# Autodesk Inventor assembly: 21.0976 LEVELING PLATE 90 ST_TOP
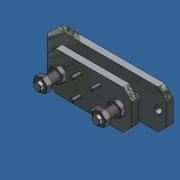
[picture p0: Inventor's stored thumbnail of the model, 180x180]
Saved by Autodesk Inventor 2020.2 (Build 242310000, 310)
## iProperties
Created: 2020-07
Part Number: 21.0976 LEVELING PLATE 90 ST_TOP
Document SubType Name: Assembly
Designer: amoles
Author: amoles
Sending System: MiniTec Maschinenbau GmbH & Co.KG
Major Version: 4.0
Minor Version: 0.0
Format Version: 0.0
Product Id: MiniTec Maschinenbau GmbH & Co.KG
Art.-Nr.: 21.0976/0
L: -
Stück: 1
5: Nivellierplatte 90 ST
7: 21.0976/0
8: MiniTec Maschinenbau GmbH & Co KG
Bestellnummer: 21.0976/0
Beschreibung: Nivellierplatte 90 ST
Länge: -
designation: hexagon screw
size: 0 x 75
standard: DIN 931
Description: hexagon screw
Artikelnr: 21.0976/0
Lieferant: MiniTec Maschinenbau GmbH & Co KG
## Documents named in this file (12)
- Y:\INVENTOR LIBRARIES\PARTS LIBRARY\FEET WHEELS FLOOR FASTENING SUPPORTS\21.0976 LEVELING PLATE 90 ST_TOP.iam
- Y:\INVENTOR LIBRARIES\PARTS LIBRARY\FEET WHEELS FLOOR FASTENING SUPPORTS\SUBCOMPONENTS\21.0976 SUBCOMPONENTS\21.0976 LEVELING PLATE 90 ST_TOP-21.ipt
- Y:\INVENTOR LIBRARIES\PARTS LIBRARY\FEET WHEELS FLOOR FASTENING SUPPORTS\SUBCOMPONENTS\21.0976 SUBCOMPONENTS\21.0976 LEVELING PLATE 90 ST_TOP 21_1.ipt
- Y:\INVENTOR LIBRARIES\PARTS LIBRARY\FEET WHEELS FLOOR FASTENING SUPPORTS\SUBCOMPONENTS\21.0976 SUBCOMPONENTS\21.0976 LEVELING PLATE 90 ST_TOP 21_2.ipt
- Y:\INVENTOR LIBRARIES\PARTS LIBRARY\FEET WHEELS FLOOR FASTENING SUPPORTS\SUBCOMPONENTS\21.0976 SUBCOMPONENTS\21.0976 LEVELING PLATE 90 ST_TOP 21_3.ipt
- Y:\INVENTOR LIBRARIES\PARTS LIBRARY\FEET WHEELS FLOOR FASTENING SUPPORTS\SUBCOMPONENTS\21.0976 SUBCOMPONENTS\21.0976 LEVELING PLATE 90 ST_TOP 21_4.ipt
- Y:\INVENTOR LIBRARIES\PARTS LIBRARY\FEET WHEELS FLOOR FASTENING SUPPORTS\SUBCOMPONENTS\21.0976 SUBCOMPONENTS\21.0976 LEVELING PLATE 90 ST_TOP 21_9.ipt
- Y:\INVENTOR LIBRARIES\PARTS LIBRARY\FEET WHEELS FLOOR FASTENING SUPPORTS\SUBCOMPONENTS\21.0976 SUBCOMPONENTS\21.0976 LEVELING PLATE 90 ST_TOP 21_10.ipt
- Y:\INVENTOR LIBRARIES\PARTS LIBRARY\FEET WHEELS FLOOR FASTENING SUPPORTS\SUBCOMPONENTS\21.0976 SUBCOMPONENTS\21.0976 LEVELING PLATE 90 ST_TOP 21_12.ipt
- Y:\INVENTOR LIBRARIES\PARTS LIBRARY\FEET WHEELS FLOOR FASTENING SUPPORTS\SUBCOMPONENTS\21.0976 SUBCOMPONENTS\21.0976 LEVELING PLATE 90 ST_TOP 21_13.ipt
- Y:\INVENTOR LIBRARIES\PARTS LIBRARY\FEET WHEELS FLOOR FASTENING SUPPORTS\SUBCOMPONENTS\21.0976 SUBCOMPONENTS\21.0976 LEVELING PLATE 90 ST_TOP 21_14.ipt
- Y:\INVENTOR LIBRARIES\PARTS LIBRARY\FASTENING ELEMENTS\SCREWS CAP\21.1204 M8X25.ipt
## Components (15 placed, 12 different names)
1. 21_1:1 — Insert:1, Insert:2, Insert:3, Insert:4
2. 21_2:1
3. 21_3:1
4. 21_4:1
5. 21_5:1
6. 21_10:1
7. 21_11:1
8. 21_13:1
9. 21_14:1
10. 21_15:1 — Insert:5
11. 21.1204  M8 x 25:1 — Insert:1
12. 21.1204  M8 x 25:2 — Insert:2
13. 21.1204  M8 x 25:3 — Insert:3
14. 21.1204  M8 x 25:4 — Insert:4
15. 21.0976 LEVELING PLATE 90 ST_TOP 21_12:2 — Insert:5
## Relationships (5: Insert 5)
- Insert:1: 21_1:1 ↔ 21.1204  M8 x 25:1
- Insert:2: 21_1:1 ↔ 21.1204  M8 x 25:2
- Insert:3: 21_1:1 ↔ 21.1204  M8 x 25:3
- Insert:4: 21_1:1 ↔ 21.1204  M8 x 25:4
- Insert:5: 21_15:1 ↔ 21.0976 LEVELING PLATE 90 ST_TOP 21_12:2
